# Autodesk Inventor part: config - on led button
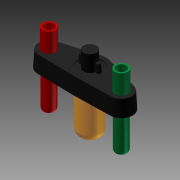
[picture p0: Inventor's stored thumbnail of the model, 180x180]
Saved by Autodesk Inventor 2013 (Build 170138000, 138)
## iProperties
Company: Autodesk Inc.
Created: 2006-01
Part Number: config - on led button
Document SubType Name: Modeling
Designer: Autodesk Inc.
Stock Number: config - on led button
Density: 1 g/cm^3
Mass: 14.3785 g
Surface Area: 78.5343 cm^2
Volume: 14.3785 cm^3
Material: Allgemein
Title: PC Demo
Author: Autodesk Inc.
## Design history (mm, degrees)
sketch "Sketch1"
  geometry: L1 (0, 14.7)-(0, -14.7) reference; L2 (-41.3, 0)-(41.3, 0) reference; L3 (-24.484, 3.713)-(-2.976, 10.069); L4 (2.976, 10.069)-(24.484, 3.713); L5 (-22.656, -9.998)-(-0.234, -10.497); L6 (0.234, -10.497)-(22.656, -9.998); A1 r 10.5 centre (0, 0) between (-2.976, 10.069) and (2.976, 10.069); A2 r 7 centre (-22.5, -3) between (-24.484, 3.713) and (-22.656, -9.998); A3 r 7 centre (22.5, -3) between (24.484, 3.713) and (22.656, -9.998)
  constraints: 8 end point, 8 point on circle, 8 tangent, 3 centre point, 2 midpoint, 1 equal radius, 1 symmetric about line
  dimensions: "d0" = 45 distance of A3.centre A2.centre; "d1" = 3 distance from line of A2.centre L2; "d2" = 14 diameter of A3; "d3" = 21 diameter of A1
extrude "Extrusion2" new body sketch "Sketch1" distance "d6" = 10; taper "d7" = 0 deg
feature "FaceDraft1" dims angle "d8" = 3 deg
sketch "Sketch2"
  geometry: C1 r 7 at (0, 0); A1 r 10.5 centre (0, 0) between (2.976, 10.069) and (-2.976, 10.069) reference
  constraints: 1 centre point, 1 coincident
  dimensions: "d9" = 14 diameter of C1
extrude "Extrusion3" join sketch "Sketch2" distance "d10" = 27; taper "d11" = 0 deg
fillet "Fillet1" dims "d12" = 5
sketch "Sketch3"
  geometry: C1 r 7.5 at (0, 0); A1 r 9.976 centre (0, 0) between (-0.222, -9.973) and (0.222, -9.973) reference
  constraints: 1 centre point, 1 coincident
  dimensions: "d13" = 15 diameter of C1
extrude "Extrusion4" cut sketch "Sketch3" distance "d14" = 0.5; taper "d15" = 0 deg
sketch "Sketch4"
  geometry: L1 (-6, 0.75)-(6, 0.75); L2 (6, 0.75)-(6, -0.75); L3 (6, -0.75)-(-6, -0.75); L4 (-6, -0.75)-(-6, 0.75); L5 (0, 14.7)-(0, -14.7) reference; L6 (-41.3, 0)-(41.3, 0) reference; C1 r 7.5 at (0, 0) reference; C2 r 4 at (0, 0)
  constraints: 8 end point, 2 parallel, 1 centre point, 1 coincident, 1 horizontal, 1 perpendicular, 2 other
  dimensions: "d16" = 8 diameter of C2; "d17" = 1.5 distance of L1.end L2.end; "d18" = 12 distance between parallel lines of L4 L2
extrude "Extrusion5" join sketch "Sketch4" distance "d19" = 10; taper "d20" = 0 deg
extrude "Extrusion6" join sketch "Sketch4" distance "d21" = 5; taper "d22" = 0 deg
feature "FaceDraft2" dims angle "d23" = 3 deg
sketch "Sketch5"
  geometry: C1 r 4 at (-22.5, -3); C2 r 4 at (22.5, -3); A1 r 6.476 centre (-22.5, -3) between (-24.335, 3.21) and (-22.644, -9.474) reference; A2 r 6.476 centre (22.5, -3) between (22.644, -9.474) and (24.335, 3.21) reference
  constraints: 2 centre point, 2 coincident, 1 equal radius
  dimensions: "d24" = 8 diameter of C1
extrude "Extrusion7" join sketch "Sketch5" distance "d25" = 12; taper "d26" = 0 deg
sketch "Sketch6"
  geometry: C1 r 3.75 at (-22.5, -3); C2 r 3.75 at (22.5, -3); A1 r 7 centre (-22.5, -3) between (-24.484, 3.713) and (-22.656, -9.998) reference; A2 r 7 centre (22.5, -3) between (22.656, -9.998) and (24.484, 3.713) reference
  constraints: 2 centre point, 2 coincident, 1 equal radius
  dimensions: "d27" = 7.5 diameter of C2
extrude "Extrusion8" join sketch "Sketch6" distance "d28" = 23; taper "d29" = 0 deg
sketch "Sketch7"
  geometry: C1 r 4 at (0, 0) reference; C2 r 4 at (45, 0) reference; C3 r 3 at (0, 0); C4 r 3 at (45, 0)
  constraints: 2 centre point, 2 coincident, 1 equal radius
  dimensions: "d30" = 6 diameter of C3
extrude "Extrusion9" cut sketch "Sketch7" distance "d31" = 44; taper "d32" = 0 deg
fillet "Fillet2" dims "d33" = 2
body "Solid1"
node "Projected Loop1"
